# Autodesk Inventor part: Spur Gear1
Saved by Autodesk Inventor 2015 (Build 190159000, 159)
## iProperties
Created: 2014-06
Part Number: Spur Gear1
Material: Steel
Document SubType Name: Modeling
Designer: User
Categories: <?xml version="1.0" encoding="UTF-16"?> <MemberInstance><Categories><FamilyTemplate><FamilyTemplateParameter ValueType="xs:double" Id="1" ObjectReferenceKey="da
Density: 1 g/cm^3
Appearance: Steel
CustomPartVersion: 1
Author: User
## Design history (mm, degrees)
sketch "Sketch1"
  geometry: C1 r 8.198 at (0, 0)
  constraints: 1 centre point
  dimensions: "d0" = 16.39526 diameter of C1 (= da_da)
extrude "Extrusion1" new body sketch "Sketch1" distance "d1" = 4 (= da_b); taper "d2" = 0 deg
workplane "Work Plane2"
sketch "Sketch2"
  geometry: C1 r 8.198 at (0, 0) reference; C2 r 7.4 at (0, 0)
  constraints: 1 centre point, 1 coincident
  dimensions: "d3" = 14.8 diameter of C2 (= da_dw)
feature "Pitch Diameter" sketch "Sketch2" dims "d4" = 10, "d5" = 0
workplane "Work Plane8"
workplane "Work Plane9"
feature "Spur Gear" dims "da_b" = 4, "da_d" = 14.62056, "da_aw" = 14.8, "da_da" = 16.39526, "da_df" = 12.80474, "da_dw" = 14.8, angle "da_beta" = 40 deg, "da_lefttooth" = 10, "da_righttooth" = 0
body "Solid1"
body "Srf1"
other parameters: "d16" = 14.8 (= da_aw), "d17" = 0, "d34" = 2.24399 (computed from da_z), "d39" = 0, "d41" = 0, "d43" = 14.8 (= da_aw), "d46" = 14.8 (= da_aw), "d47" = 0, "d48" = 0
